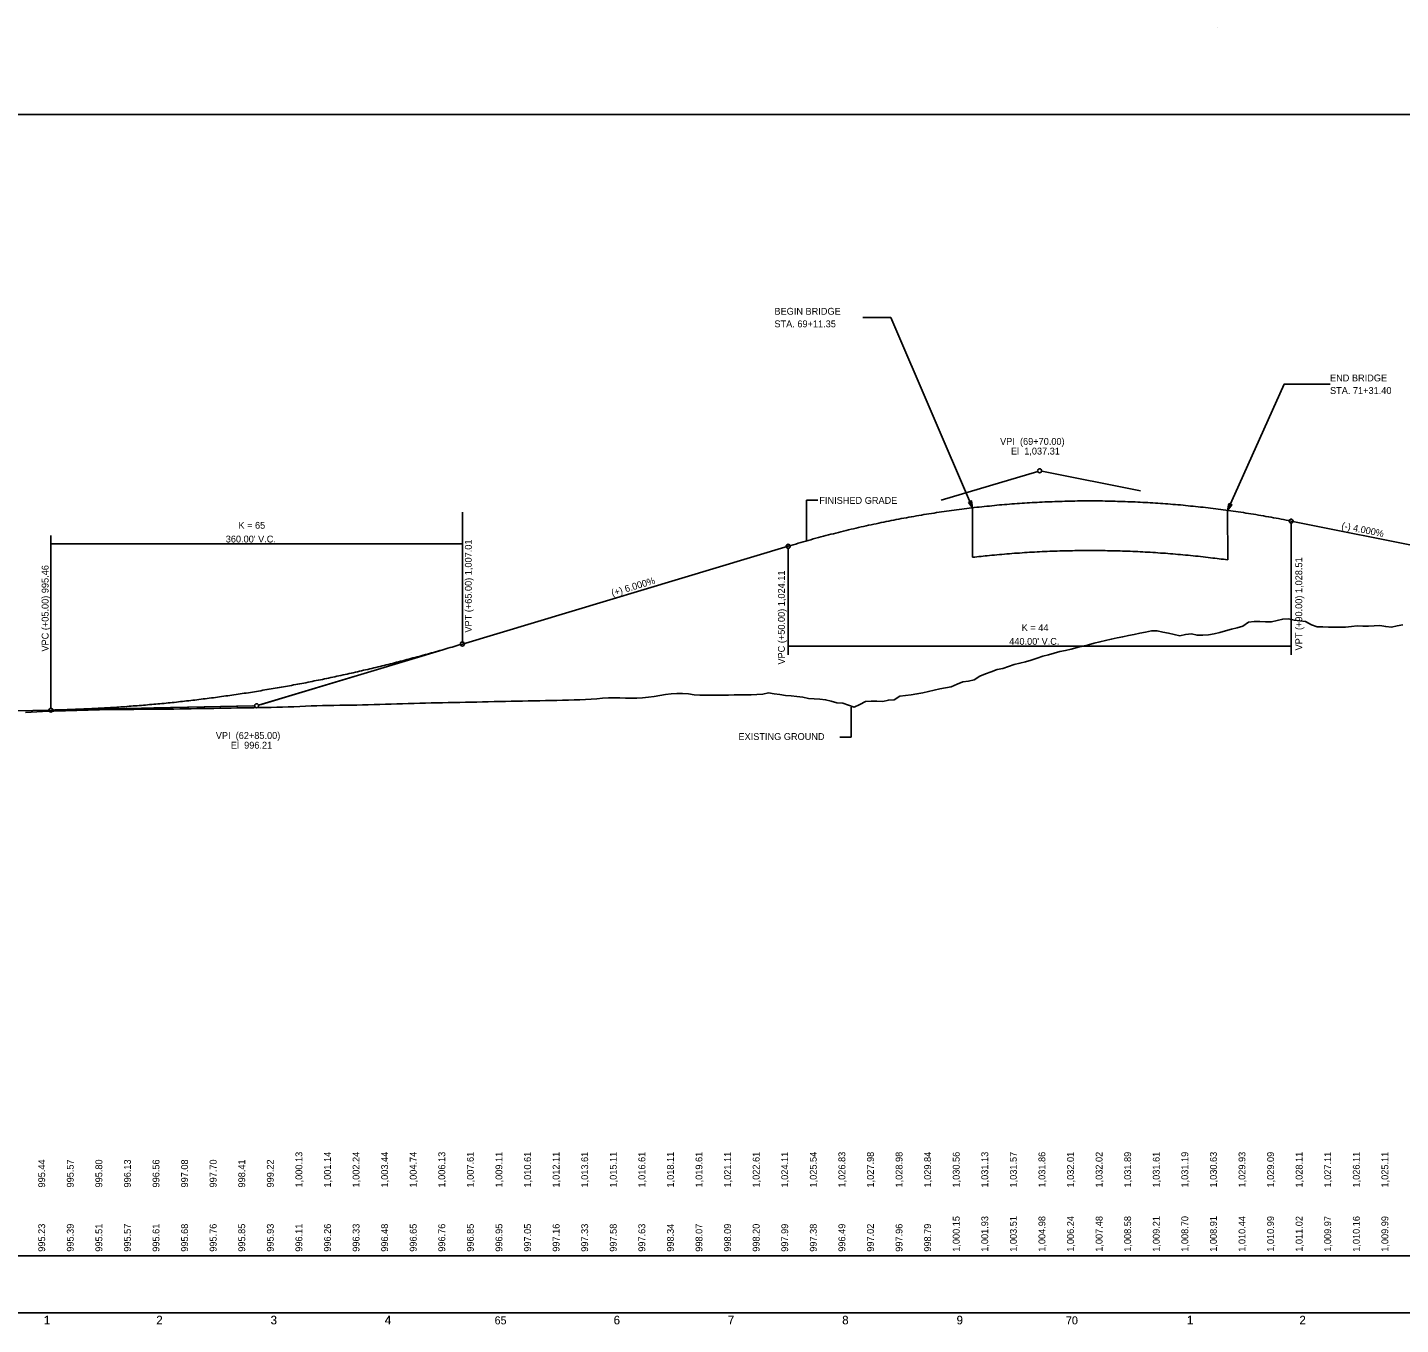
# Model space of a CAD drawing. Extents: x 889661 to 1611291, y 880491 to 1094402.
# Drawn here: x 891561 to 892763, y 880491 to 881625 of the extents above; entities that cross this region are included whole.
import ezdxf

# ---------------------------------------------------------------- set-up
doc = ezdxf.new("R2010")
doc.units = 0
for name, color, linetype in [('Default', 7, 'Continuous'), ('Level 52', 7, 'Continuous'), ('RD_DDB_EX_Tx', 7, 'Continuous'), ('RD_DDB_GradeTX', 7, 'Continuous'), ('RD_DDB_PI', 7, 'Continuous'), ('RD_DDB_PR_Tx', 7, 'Continuous'), ('RD_DDB_Profile_EX', 7, 'Continuous'), ('RD_DDB_Profile_PR', 7, 'Continuous'), ('RD_DDB_StaTX', 7, 'Continuous'), ('RD_DDB_StripGrade_EX', 7, 'Continuous'), ('RD_DDB_StripGrade_PR', 7, 'Continuous'), ('RD_DDB_VCLbl', 7, 'Continuous'), ('RD_GPK_Profile_Cell', 7, 'Continuous'), ('RD_PD_Bridge', 7, 'Continuous'), ('RD_SHT_TX', 7, 'Continuous')]:
    doc.layers.add(name, color=color, linetype=linetype)

msp = doc.modelspace()

# ---------------------------------------------------------------- linework, layer by layer
at = {"layer": 'Default'}
msp.add_lwpolyline([(891476.9, 880551.1), (892976.9, 880551.1), (892976.9, 881549.3), (891476.9, 881549.3)], close=True, dxfattribs=at)
at = {"layer": 'Level 52'}
for p, q in [((891924.8, 881081), (891765.8, 881033.3)), ((891592, 881028.6), (891757.9, 881032))]:
    msp.add_line(p, q, dxfattribs=at)
at = {"layer": 'RD_DDB_EX_Tx'}
for p, q in [((892281.9, 881004.7), (892281.9, 881030.8)), ((892272.2, 881004.7), (892281.9, 881004.7))]:
    msp.add_line(p, q, dxfattribs=at)
at = {"layer": 'RD_DDB_PI'}
for p, q in [((892360.7, 881211.8), (892445.3, 881237.1)), ((892535.2, 881220), (892448.7, 881237.3)), ((891848.2, 881058), (891763.6, 881032.6)), ((891672, 881030.2), (891760.2, 881032.1))]:
    msp.add_line(p, q, dxfattribs=at)
for centre in [(892446.9, 881237.6), (891761.9, 881032.1)]:
    msp.add_circle(centre, 1.75, dxfattribs=at)
at = {"layer": 'RD_DDB_PR_Tx'}
for p, q in [((892242.8, 881212), (892242.8, 881176.2)), ((892252.8, 881212), (892242.8, 881212))]:
    msp.add_line(p, q, dxfattribs=at)
at = {"layer": 'RD_DDB_Profile_EX'}
for points in [[(892419.6, 881066.4), (892424.6, 881068.1), (892429.6, 881069.3), (892434.6, 881070.6), (892439.6, 881072), (892444.6, 881073.7), (892449.6, 881075.4), (892454.6, 881076.7), (892459.6, 881078.2), (892464.6, 881079.6), (892469.6, 881080.5), (892474.6, 881081.7), (892479.6, 881083), (892484.6, 881084.3), (892489.6, 881085.5), (892494.6, 881086.8), (892499.6, 881087.9), (892504.6, 881089.1), (892509.6, 881090.2), (892514.6, 881091.4), (892519.6, 881092.5), (892524.6, 881093.5), (892529.6, 881094.5), (892534.6, 881095.5), (892539.6, 881096.5), (892544.6, 881097.5), (892549.6, 881097.6), (892554.6, 881096.5), (892559.6, 881095.5), (892564.6, 881094.4), (892569.6, 881093.3), (892574.6, 881094.3), (892579.6, 881094.9), (892584.6, 881093.7), (892589.6, 881093.7), (892594.6, 881094.2), (892599.6, 881095.1), (892604.6, 881096.1), (892609.6, 881097.7), (892614.6, 881099.2), (892619.6, 881100.3), (892624.6, 881101.7), (892629.6, 881105.1), (892634.6, 881105.7), (892639.6, 881105.7), (892644.6, 881105.6), (892649.6, 881105.4), (892654.6, 881106.6), (892659.6, 881107.9), (892664.6, 881108), (892669.6, 881107.1), (892674.6, 881106.4), (892679.6, 881105.8), (892684.6, 881103), (892689.6, 881101.2), (892694.6, 881101), (892699.6, 881100.9), (892704.6, 881100.8), (892709.6, 881100.8), (892714.6, 881100.9), (892719.6, 881101.3), (892724.6, 881101.9), (892729.6, 881101.8), (892734.6, 881101.7), (892739.6, 881102), (892744.6, 881102.2), (892749.6, 881101.3), (892754.6, 881100.7), (892759.6, 881102), (892764.6, 881103)], [(891919.6, 881034.7), (891924.6, 881034.8), (891929.6, 881034.9), (891934.6, 881035), (891939.6, 881035.1), (891944.6, 881035.2), (891949.6, 881035.2), (891954.6, 881035.3), (891959.6, 881035.4), (891964.6, 881035.6), (891969.6, 881035.7), (891974.6, 881035.8), (891979.6, 881035.9), (891984.6, 881036), (891989.6, 881036.1), (891994.6, 881036.2), (891999.6, 881036.3), (892004.6, 881036.4), (892009.6, 881036.5), (892014.6, 881036.6), (892019.6, 881036.7), (892024.6, 881036.8), (892029.6, 881036.9), (892034.6, 881037), (892039.6, 881037.2), (892044.6, 881037.4), (892049.6, 881037.6), (892054.6, 881037.8), (892059.6, 881038.2), (892064.6, 881038.7), (892069.6, 881039.1), (892074.6, 881039), (892079.6, 881038.9), (892084.6, 881038.8), (892089.6, 881038.7), (892094.6, 881038.8), (892099.6, 881038.9), (892104.6, 881039.6), (892109.6, 881040.3), (892114.6, 881041.1), (892119.6, 881041.9), (892124.6, 881042.6), (892129.6, 881042.9), (892134.6, 881042.8), (892139.6, 881042.4), (892144.6, 881041.8), (892149.6, 881041.4), (892154.6, 881041.3), (892159.6, 881041.3), (892164.6, 881041.4), (892169.6, 881041.4), (892174.6, 881041.5), (892179.6, 881041.6), (892184.6, 881041.6), (892189.6, 881041.7), (892194.6, 881041.8), (892199.6, 881041.9), (892204.6, 881042.2), (892209.6, 881043.3), (892214.6, 881042.6), (892219.6, 881041.9), (892224.6, 881041.2), (892229.6, 881040.7), (892234.6, 881040.3), (892239.6, 881039.6), (892244.6, 881038.6), (892249.6, 881038.1), (892254.6, 881037.8), (892259.6, 881037.3), (892264.6, 881036), (892269.6, 881034.7), (892274.6, 881034.3), (892279.6, 881032.5), (892284.6, 881030.9), (892289.6, 881033.1), (892294.6, 881035.7), (892299.6, 881036.2), (892304.6, 881036.1), (892309.6, 881035.9), (892314.6, 881037), (892319.6, 881037.4), (892324.6, 881040.6), (892329.6, 881041.1), (892334.6, 881041.8), (892339.6, 881042.4), (892344.6, 881043.3), (892349.6, 881044.5), (892354.6, 881045.7), (892359.6, 881046.8), (892364.6, 881047.8), (892369.6, 881048.8), (892374.6, 881050.9), (892379.6, 881052.9), (892384.6, 881053.7), (892389.6, 881054.8), (892394.6, 881058), (892399.6, 881059.9), (892404.6, 881061.7), (892409.6, 881063.8), (892414.6, 881064.7), (892419.6, 881066.4)], [(891559.6, 881026.2), (891564.6, 881026.5), (891569.6, 881026.8), (891574.6, 881027.1), (891579.6, 881027.3), (891584.6, 881027.5), (891589.6, 881027.7), (891594.6, 881027.8), (891599.6, 881028), (891604.6, 881028.1), (891609.6, 881028.2), (891614.6, 881028.3), (891619.6, 881028.4), (891624.6, 881028.6), (891629.6, 881028.7), (891634.6, 881028.7), (891639.6, 881028.8), (891644.6, 881028.8), (891649.6, 881028.9), (891654.6, 881028.9), (891659.6, 881029), (891664.6, 881029), (891669.6, 881029), (891674.6, 881029.1), (891679.6, 881029.1), (891684.6, 881029.2), (891689.6, 881029.2), (891694.6, 881029.3), (891699.6, 881029.4), (891704.6, 881029.5), (891709.6, 881029.6), (891714.6, 881029.7), (891719.6, 881029.8), (891724.6, 881029.8), (891729.6, 881029.9), (891734.6, 881030), (891739.6, 881030.1), (891744.6, 881030.2), (891749.6, 881030.3), (891754.6, 881030.3), (891759.6, 881030.4), (891764.6, 881030.5), (891769.6, 881030.6), (891774.6, 881030.7), (891779.6, 881030.8), (891784.6, 881030.9), (891789.6, 881031.1), (891794.6, 881031.3), (891799.6, 881031.5), (891804.6, 881031.7), (891809.6, 881031.9), (891814.6, 881032.1), (891819.6, 881032.2), (891824.6, 881032.3), (891829.6, 881032.4), (891834.6, 881032.5), (891839.6, 881032.5), (891844.6, 881032.6), (891849.6, 881032.7), (891854.6, 881032.8), (891859.6, 881032.9), (891864.6, 881033.1), (891869.6, 881033.2), (891874.6, 881033.4), (891879.6, 881033.5), (891884.6, 881033.7), (891889.6, 881033.9), (891894.6, 881034.1), (891899.6, 881034.2), (891904.6, 881034.4), (891909.6, 881034.5), (891914.6, 881034.6), (891919.6, 881034.7)]]:
    msp.add_lwpolyline(points, dxfattribs=at)
at = {"layer": 'RD_DDB_Profile_PR'}
for p, q in [((892666.9, 881193.6), (892801.9, 881166.6)), ((891941.9, 881086.1), (892226.9, 881171.6)), ((891111.9, 881018.4), (891581.9, 881028.3))]:
    msp.add_line(p, q, dxfattribs=at)
for points in [[(892226.9, 881171.6), (892235.7, 881174.2), (892244.5, 881176.7), (892253.3, 881179.2), (892262.1, 881181.5), (892270.9, 881183.7), (892279.7, 881185.9), (892288.5, 881188), (892297.3, 881189.9), (892306.1, 881191.8), (892314.9, 881193.6), (892323.7, 881195.3), (892332.5, 881197), (892341.3, 881198.5), (892350.1, 881200), (892358.9, 881201.3), (892367.7, 881202.6), (892376.5, 881203.8), (892385.3, 881204.9), (892394.1, 881205.9), (892402.9, 881206.8), (892411.7, 881207.7), (892420.5, 881208.4), (892429.3, 881209.1), (892438.1, 881209.6), (892446.9, 881210.1), (892455.7, 881210.5), (892464.5, 881210.8), (892473.3, 881211.1), (892482.1, 881211.2), (892490.9, 881211.2), (892499.7, 881211.2), (892508.5, 881211.1), (892517.3, 881210.8), (892526.1, 881210.5), (892534.9, 881210.1), (892543.7, 881209.6), (892552.5, 881209.1), (892561.3, 881208.4), (892570.1, 881207.7), (892578.9, 881206.8), (892587.7, 881205.9), (892596.5, 881204.9), (892605.3, 881203.8), (892614.1, 881202.6), (892622.9, 881201.3), (892631.7, 881200), (892640.5, 881198.5), (892649.3, 881197), (892658.1, 881195.3), (892666.9, 881193.6)], [(891581.9, 881028.3), (891589.1, 881028.5), (891596.3, 881028.7), (891603.5, 881029), (891610.7, 881029.3), (891617.9, 881029.6), (891625.1, 881030), (891632.3, 881030.4), (891639.5, 881030.8), (891646.7, 881031.3), (891653.9, 881031.9), (891661.1, 881032.4), (891668.3, 881033.1), (891675.5, 881033.7), (891682.7, 881034.4), (891689.9, 881035.1), (891697.1, 881035.9), (891704.3, 881036.7), (891711.5, 881037.6), (891718.7, 881038.5), (891725.9, 881039.4), (891733.1, 881040.4), (891740.3, 881041.4), (891747.5, 881042.5), (891754.7, 881043.5), (891761.9, 881044.7), (891769.1, 881045.9), (891776.3, 881047.1), (891783.5, 881048.3), (891790.7, 881049.6), (891797.9, 881051), (891805.1, 881052.3), (891812.3, 881053.8), (891819.5, 881055.2), (891826.7, 881056.7), (891833.9, 881058.3), (891841.1, 881059.8), (891848.3, 881061.4), (891855.5, 881063.1), (891862.7, 881064.8), (891869.9, 881066.5), (891877.1, 881068.3), (891884.3, 881070.1), (891891.5, 881072), (891898.7, 881073.9), (891905.9, 881075.8), (891913.1, 881077.8), (891920.3, 881079.8), (891927.5, 881081.9), (891934.7, 881084), (891941.9, 881086.1)]]:
    msp.add_spline(points, degree=3, dxfattribs=at)
at = {"layer": 'RD_DDB_StripGrade_PR'}
msp.add_line((892602.9, 881625.3), (892602.9, 881625.3), dxfattribs=at)
msp.add_line((892602.9, 881625.3), (892602.9, 881625.3), dxfattribs=at)
msp.add_line((892602.9, 881625.3), (892602.9, 881625.3), dxfattribs=at)
msp.add_line((892602.9, 881625.3), (892602.9, 881625.3), dxfattribs=at)
msp.add_line((892602.9, 881625.3), (892602.9, 881625.3), dxfattribs=at)
msp.add_line((892602.9, 881625.3), (892602.9, 881625.3), dxfattribs=at)
msp.add_line((892602.9, 881625.3), (892602.9, 881625.3), dxfattribs=at)
msp.add_line((892602.9, 881625.3), (892602.9, 881625.3), dxfattribs=at)
msp.add_line((892602.9, 881625.3), (892602.9, 881625.3), dxfattribs=at)
msp.add_line((892602.9, 881625.3), (892602.9, 881625.3), dxfattribs=at)
at = {"layer": 'RD_DDB_VCLbl'}
for p, q in [((891941.9, 881201.5), (891941.9, 881087.9)), ((891581.9, 881181.1), (891581.9, 881030.1)), ((892666.9, 881076.6), (892666.9, 881191.9)), ((891581.9, 881173.6), (891941.9, 881173.6)), ((892226.9, 881076.6), (892226.9, 881169.9)), ((892226.9, 881084.1), (892666.9, 881084.1))]:
    msp.add_line(p, q, dxfattribs=at)
for centre in [(892666.9, 881193.6), (892226.9, 881171.6), (891941.9, 881086.1), (891581.9, 881028.3)]:
    msp.add_circle(centre, 1.75, dxfattribs=at)
at = {"layer": 'RD_GPK_Profile_Cell'}
msp.add_line((890419.6, 880501.1), (893505.3, 880501.1), dxfattribs=at)
at = {"layer": 'RD_PD_Bridge'}
for p, q in [((892388.3, 881162), (892388.3, 881205.2)), ((892611.4, 881159.8), (892611.3, 881203))]:
    msp.add_line(p, q, dxfattribs=at)
msp.add_spline([(892388.3, 881162), (892402.9, 881163.5), (892411.7, 881164.3), (892420.5, 881165.1), (892429.3, 881165.7), (892438.1, 881166.3), (892446.9, 881166.8), (892455.7, 881167.2), (892464.5, 881167.5), (892473.3, 881167.7), (892482.1, 881167.8), (892490.9, 881167.9), (892499.7, 881167.8), (892508.5, 881167.7), (892517.3, 881167.5), (892526.1, 881167.2), (892534.9, 881166.8), (892543.7, 881166.3), (892552.5, 881165.7), (892561.3, 881165.1), (892570.1, 881164.3), (892578.9, 881163.5), (892587.7, 881162.6), (892596.5, 881161.5), (892611.4, 881159.8)], degree=3, dxfattribs=at)
at = {"layer": 'RD_SHT_TX'}
for points in [[(892292.3, 881371.6), (892316.6, 881371.6), (892388.3, 881205.2)], [(892700.9, 881313.3), (892660.7, 881313.3), (892611.3, 881203)]]:
    msp.add_lwpolyline(points, dxfattribs=at)
for points in [[(892384.6, 881210), (892388.3, 881205.2), (892387.4, 881211.2)], [(892612.3, 881208.9), (892611.3, 881203), (892615.1, 881207.7)]]:
    msp.add_lwpolyline(points, close=True, dxfattribs=at)

# ---------------------------------------------------------------- texts
at = {"layer": 'RD_DDB_EX_Tx'}
msp.add_text('EXISTING GROUND', height=6, dxfattribs=at).set_placement((892183.4, 881002.2))
at = {"layer": 'RD_DDB_GradeTX'}
for s, rotation, p in [('(-) 4.000%', 348.6902, (892710.6, 881186.9)), ('(+) 6.000%', 16.6992, (892073.2, 881127.7))]:
    msp.add_text(s, height=6, rotation=rotation, dxfattribs=at).set_placement(p)
at = {"layer": 'RD_DDB_PI'}
for s, p in [('VPI  (69+70.00)', (892412.3, 881260.3)), ('El  1,037.31', (892421.8, 881251.8)), ('VPI  (62+85.00)', (891726.2, 881003.1)), ('El  996.21', (891739.4, 880994.6))]:
    msp.add_text(s, height=6, dxfattribs=at).set_placement(p)
at = {"layer": 'RD_DDB_PR_Tx'}
msp.add_text('FINISHED GRADE', height=6, dxfattribs=at).set_placement((892254.2, 881208.7))
at = {"layer": 'RD_DDB_StaTX'}
for s, height, p in [('1', 7.5, (891575.6, 880491.1)), ('1', 7.5, (891575.6, 880491.1)), ('1', 7.5, (891575.9, 880491.1)), ('2', 7.5, (891674.1, 880491.1)), ('2', 7.5, (891674.2, 880491.1)), ('2', 7.5, (891674.2, 880491.1)), ('3', 7.5, (891774.1, 880491.1)), ('3', 7.5, (891774.2, 880491.1)), ('3', 7.5, (891774.2, 880491.1)), ('4', 7.5, (891873.9, 880491.1)), ('4', 7.5, (891874.2, 880491.1)), ('4', 7.5, (891874.2, 880491.1)), ('65', 7, (891970.1, 880491.1)), ('65', 7, (891970.1, 880491.1)), ('65', 7, (891970.1, 880491.1)), ('6', 7.5, (892074.2, 880491.1)), ('6', 7.5, (892074.2, 880491.1)), ('6', 7.5, (892074.3, 880491.1)), ('7', 7.5, (892174.1, 880491.1)), ('7', 7.5, (892174.2, 880491.1)), ('7', 7.5, (892174.2, 880491.1)), ('8', 7.5, (892274.1, 880491.1)), ('8', 7.5, (892274.2, 880491.1)), ('8', 7.5, (892274.2, 880491.1)), ('9', 7.5, (892374.2, 880491.1)), ('9', 7.5, (892374.2, 880491.1)), ('9', 7.5, (892374.3, 880491.1)), ('70', 7, (892469.9, 880491.1)), ('70', 7, (892470, 880491.1)), ('70', 7, (892470, 880491.1)), ('1', 7.5, (892575.6, 880491.1)), ('1', 7.5, (892575.6, 880491.1)), ('1', 7.5, (892575.9, 880491.1)), ('2', 7.5, (892674.1, 880491.1)), ('2', 7.5, (892674.2, 880491.1)), ('2', 7.5, (892674.2, 880491.1))]:
    msp.add_text(s, height=height, dxfattribs=at).set_placement(p)
at = {"layer": 'RD_DDB_StripGrade_EX'}
for s, p in [('1,000.15', (892376.9, 880554.6)), ('1,001.93', (892401.9, 880554.6)), ('1,003.51', (892426.9, 880554.6)), ('1,004.98', (892451.9, 880554.6)), ('1,006.24', (892476.9, 880554.6)), ('1,007.48', (892501.9, 880554.6)), ('1,008.58', (892526.9, 880554.6)), ('1,009.21', (892551.9, 880554.6)), ('1,008.70', (892576.9, 880554.6)), ('1,008.91', (892601.9, 880554.6)), ('1,010.44', (892626.9, 880554.6)), ('1,010.99', (892651.9, 880554.6)), ('1,011.02', (892676.9, 880554.6)), ('1,009.97', (892701.9, 880554.6)), ('1,010.16', (892726.9, 880554.6)), ('1,009.99', (892751.9, 880554.6)), ('995.23', (891576.9, 880554.6)), ('995.39', (891601.9, 880554.6)), ('995.51', (891626.9, 880554.6)), ('995.57', (891651.9, 880554.6)), ('995.61', (891676.9, 880554.6)), ('995.68', (891701.9, 880554.6)), ('995.76', (891726.9, 880554.6)), ('995.85', (891751.9, 880554.6)), ('995.93', (891776.9, 880554.6)), ('996.11', (891801.9, 880554.6)), ('996.26', (891826.9, 880554.6)), ('996.33', (891851.9, 880554.6)), ('996.48', (891876.9, 880554.6)), ('996.65', (891901.9, 880554.6)), ('996.76', (891926.9, 880554.6)), ('996.85', (891951.9, 880554.6)), ('996.95', (891976.9, 880554.6)), ('997.05', (892001.9, 880554.6)), ('997.16', (892026.9, 880554.6)), ('997.33', (892051.9, 880554.6)), ('997.58', (892076.9, 880554.6)), ('997.63', (892101.9, 880554.6)), ('998.34', (892126.9, 880554.6)), ('998.07', (892151.9, 880554.6)), ('998.09', (892176.9, 880554.6)), ('998.20', (892201.9, 880554.6)), ('997.99', (892226.9, 880554.6)), ('997.38', (892251.9, 880554.6)), ('996.49', (892276.9, 880554.6)), ('997.02', (892301.9, 880554.6)), ('997.96', (892326.9, 880554.6)), ('998.79', (892351.9, 880554.6))]:
    msp.add_text(s, height=6, rotation=90, dxfattribs=at).set_placement(p)
at = {"layer": 'RD_DDB_StripGrade_PR'}
for s, p in [('1,000.13', (891801.9, 880610.8)), ('1,001.14', (891826.9, 880610.8)), ('1,002.24', (891851.9, 880610.8)), ('1,003.44', (891876.9, 880610.8)), ('1,004.74', (891901.9, 880610.8)), ('1,006.13', (891926.9, 880610.8)), ('1,007.61', (891951.9, 880610.8)), ('1,009.11', (891976.9, 880610.8)), ('1,010.61', (892001.9, 880610.8)), ('1,012.11', (892026.9, 880610.8)), ('1,013.61', (892051.9, 880610.8)), ('1,015.11', (892076.9, 880610.8)), ('1,016.61', (892101.9, 880610.8)), ('1,018.11', (892126.9, 880610.8)), ('1,019.61', (892151.9, 880610.8)), ('1,021.11', (892176.9, 880610.8)), ('1,022.61', (892201.9, 880610.8)), ('1,024.11', (892226.9, 880610.8)), ('1,025.54', (892251.9, 880610.8)), ('1,026.83', (892276.9, 880610.8)), ('1,027.98', (892301.9, 880610.8)), ('1,028.98', (892326.9, 880610.8)), ('1,029.84', (892351.9, 880610.8)), ('1,030.56', (892376.9, 880610.8)), ('1,031.13', (892401.9, 880610.8)), ('1,031.57', (892426.9, 880610.8)), ('1,031.86', (892451.9, 880610.8)), ('1,032.01', (892476.9, 880610.8)), ('1,032.02', (892501.9, 880610.8)), ('1,031.89', (892526.9, 880610.8)), ('1,031.61', (892551.9, 880610.8)), ('1,031.19', (892576.9, 880610.8)), ('1,030.63', (892601.9, 880610.8)), ('1,029.93', (892626.9, 880610.8)), ('1,029.09', (892651.9, 880610.8)), ('1,028.11', (892676.9, 880610.8)), ('1,027.11', (892701.9, 880610.8)), ('1,026.11', (892726.9, 880610.8)), ('1,025.11', (892751.9, 880610.8)), ('995.44', (891576.9, 880610.8)), ('995.57', (891601.9, 880610.8)), ('995.80', (891626.9, 880610.8)), ('996.13', (891651.9, 880610.8)), ('996.56', (891676.9, 880610.8)), ('997.08', (891701.9, 880610.8)), ('997.70', (891726.9, 880610.8)), ('998.41', (891751.9, 880610.8)), ('999.22', (891776.9, 880610.8))]:
    msp.add_text(s, height=6, rotation=90, dxfattribs=at).set_placement(p)
at = {"layer": 'RD_DDB_VCLbl'}
for s, p in [('K = 65', (891746, 881186.9)), ("360.00' V.C.", (891734.9, 881174.9)), ('K = 44', (892431.2, 881097.4)), ("440.00' V.C.", (892420.3, 881085.4))]:
    msp.add_text(s, height=6, dxfattribs=at).set_placement(p)
for s, p in [('VPT (+65.00) 1,007.01', (891950.1, 881096.1)), ('VPT (+90.00) 1,028.51', (892676.6, 881080.5)), ('VPC (+05.00) 995.46', (891579.9, 881079.5)), ('VPC (+50.00) 1,024.11', (892224, 881068.1))]:
    msp.add_text(s, height=6, rotation=90, dxfattribs=at).set_placement(p)
at = {"layer": 'RD_SHT_TX'}
for s, p in [('BEGIN BRIDGE', (892214.9, 881374.1)), ('STA. 69+11.35', (892214.9, 881363.1)), ('END BRIDGE', (892700.9, 881315.8)), ('STA. 71+31.40', (892700.9, 881304.8))]:
    msp.add_text(s, height=6, rotation=360, dxfattribs=at).set_placement(p)

doc.saveas('drawing.dxf')
